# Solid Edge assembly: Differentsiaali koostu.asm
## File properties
Author: Türk
Template: Iso Assembly.asm
Last saved by: Türk
Revision: 23
Application: Solid Edge
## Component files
difri suurhammakas.par
Diffrisise1.par
Kuullaager Tagu.asm
lliliigend.par
llpar.par
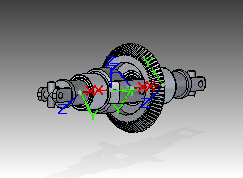
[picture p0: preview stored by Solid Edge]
